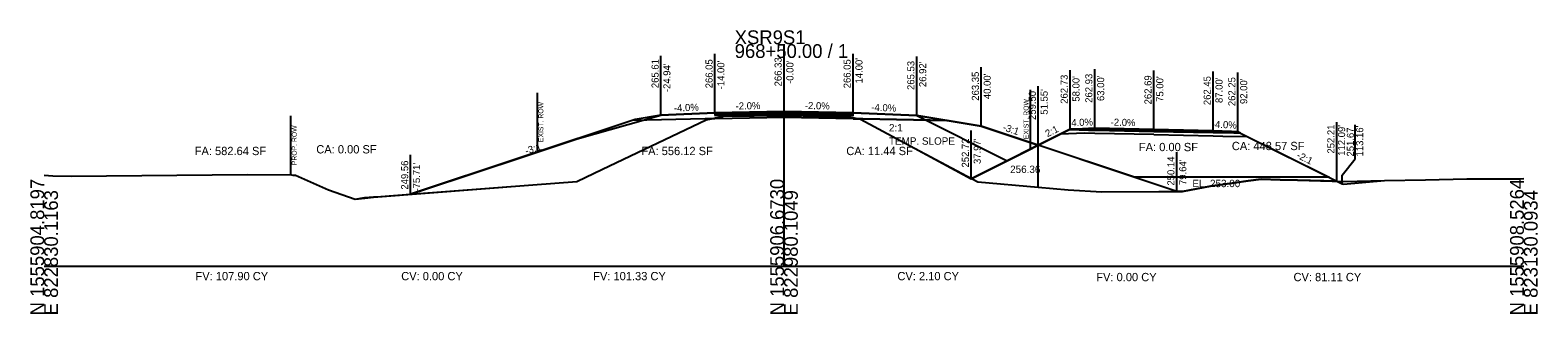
# Model space of a CAD drawing. Extents: x -26 to 823017, y -16 to 1558356.
# Drawn here: x 997.2 to 1302.8, y 8990.3 to 9047.8 of the extents above; entities that cross this region are included whole.
import ezdxf

# ---------------------------------------------------------------- set-up
doc = ezdxf.new("R2010")
doc.units = 0
for name, color, linetype in [('1', 7, 'Continuous'), ('ASPHALT_19MM1', 7, 'Continuous'), ('ASPHALT_9_5MM1', 7, 'Continuous'), ('CONST_DCH', 7, 'Continuous'), ('CONST_LV3', 7, 'Continuous'), ('Draft_XS_Grid', 7, 'Continuous'), ('DTM_CORRIDOR', 7, 'Continuous'), ('DTM_P_FINISHED_GRADE2', 7, 'Continuous'), ('DTM_X_GROUND', 7, 'Continuous'), ('SLOPE_STAKES_FILL', 7, 'Continuous'), ('X_PROFILES_1', 7, 'Continuous'), ('X_TRANS_EOP', 7, 'Continuous'), ('XS_CELL', 7, 'Continuous'), ('XS_M_SHAPES_EARTHWORK', 7, 'Continuous'), ('XS_P_DR_GRAVEL', 7, 'Continuous'), ('XS_P_GROUND', 7, 'Continuous'), ('XS_P_NULL_POINT', 7, 'Continuous'), ('XS_P_ROW', 7, 'Continuous'), ('XS_P_SHOULDER', 7, 'Continuous'), ('XS_P_SUBGRADE_GRANULAR', 7, 'Continuous'), ('XS_P_SUBGRADE_UNDERCUT', 7, 'Continuous'), ('XS_P_TX_CLEARZONE', 7, 'Continuous'), ('XS_P_TX_FS_BS', 7, 'Continuous'), ('XS_SHEET_EW_TX_AREA', 7, 'Continuous'), ('XS_SHEET_EW_TX_VOLUME', 7, 'Continuous'), ('XS_X_ROW', 7, 'Continuous')]:
    doc.layers.add(name, color=color, linetype=linetype)

msp = doc.modelspace()

# ---------------------------------------------------------------- linework, layer by layer
at = {"layer": '1'}
msp.add_lwpolyline([(1136, 9030.76), (1136, 9030.76), (1136, 9030.76), (1150, 9031.04), (1164, 9030.76), (1164, 9030.76), (1164, 9030.76), (1164, 9030.92), (1164, 9030.92), (1150, 9031.2), (1136, 9030.92), (1136, 9030.92), (1136, 9030.76)], dxfattribs=at)
at = {"layer": 'ASPHALT_19MM1'}
for points in [[(1136, 9030.55), (1136, 9030.55), (1136, 9030.55), (1150, 9030.83), (1164, 9030.55), (1164, 9030.55), (1164, 9030.55), (1164, 9030.76), (1164, 9030.76), (1150, 9031.04), (1136, 9030.76), (1136, 9030.76), (1136, 9030.55)], [(1213, 9027.56), (1225, 9027.32), (1237, 9027.08), (1237, 9027.28), (1225, 9027.52), (1213, 9027.76), (1213, 9027.56)]]:
    msp.add_lwpolyline(points, dxfattribs=at)
at = {"layer": 'ASPHALT_9_5MM1'}
msp.add_lwpolyline([(1136, 9030.92), (1136, 9030.92), (1136, 9030.92), (1150, 9031.2), (1164, 9030.92), (1164, 9030.92), (1164, 9030.92), (1164, 9031.05), (1164, 9031.05), (1150, 9031.33), (1136, 9031.05), (1136, 9031.05), (1136, 9030.92)], dxfattribs=at)
at = {"layer": 'CONST_LV3'}
for points in [[(1150, 9031.33), (1164, 9031.05)], [(1176.92, 9030.53), (1164, 9031.05), (1164, 9031.05)], [(1190, 9028.35), (1183.11, 9029.5), (1183.11, 9029.5)], [(1187.97, 9017.72), (1192.97, 9020.22), (1208, 9027.73), (1209.25, 9027.78), (1213, 9027.93)], [(1201.55, 9024.5), (1201.55, 9024.5), (1208, 9027.73), (1209.25, 9027.78), (1213, 9027.93), (1222.01, 9027.75), (1225, 9027.69), (1234.01, 9027.23), (1237, 9027.08), (1238.25, 9027.12), (1242, 9027.25), (1256.97, 9019.77), (1263.16, 9016.67), (1263.42, 9016.6), (1271.75, 9017.33), (1280.09, 9017.49), (1288.44, 9017.66), (1299.2, 9017.72), (1300, 9017.74)], [(1242, 9027.25), (1262.09, 9017.21)], [(1000, 9018.4), (1001.79, 9018.3), (1005.5, 9018.26), (1041.22, 9018.54), (1050.13, 9018.47), (1050.44, 9018.46), (1050.95, 9018.46), (1057.63, 9015.48), (1063.04, 9013.57), (1064.99, 9013.79), (1066.77, 9013.99), (1067.35, 9014.04), (1074.29, 9014.56)]]:
    msp.add_lwpolyline(points, dxfattribs=at)
at = {"layer": 'DTM_P_FINISHED_GRADE2'}
msp.add_lwpolyline([(1074.29, 9014.56), (1074.29, 9014.56), (1108.06, 9025.82), (1125.06, 9030.61), (1136, 9031.05), (1150, 9031.33), (1164, 9031.05), (1176.92, 9030.53), (1190, 9028.35), (1201.55, 9024.5)], dxfattribs=at)
at = {"layer": 'DTM_X_GROUND'}
for points in [[(1000, 9018.4), (1001.79, 9018.3), (1005.5, 9018.26), (1041.22, 9018.54), (1050.13, 9018.47), (1050.44, 9018.46), (1050.95, 9018.46), (1057.63, 9015.48), (1063.04, 9013.57), (1064.99, 9013.93), (1066.77, 9014.01), (1067.35, 9014.04), (1074.29, 9014.56), (1074.29, 9014.56), (1089.77, 9019.72), (1094.89, 9021.43), (1098.94, 9022.78), (1108.06, 9025.82), (1125.06, 9030.61), (1125.06, 9030.61), (1125.06, 9030.61), (1136, 9031.05), (1150, 9031.33), (1150, 9031.33), (1150, 9031.33), (1164, 9031.05), (1164, 9031.05), (1176.92, 9030.53), (1176.92, 9030.53), (1190, 9028.35), (1190, 9028.35), (1201.55, 9024.5), (1201.55, 9024.5), (1208, 9027.73), (1209.25, 9027.78), (1213, 9027.93), (1222.01, 9027.75), (1225, 9027.69), (1234.01, 9027.23), (1237, 9027.08), (1238.25, 9027.12), (1242, 9027.25), (1256.97, 9019.77), (1263.16, 9016.67), (1263.42, 9016.6), (1271.75, 9017.33), (1280.09, 9017.49), (1288.44, 9017.66), (1299.2, 9017.72), (1300, 9017.74)], [(1000, 9018.4), (1001.79, 9018.3), (1005.5, 9018.26), (1041.22, 9018.54), (1050.13, 9018.47), (1050.44, 9018.46), (1050.95, 9018.46), (1057.63, 9015.48), (1063.04, 9013.57), (1066.77, 9013.99), (1099.1, 9016.46), (1107.98, 9017.16), (1113.22, 9019.62), (1134.23, 9029.63), (1137.38, 9030.33), (1137.5, 9030.36), (1137.69, 9030.4), (1150.25, 9030.55), (1150.48, 9030.55), (1150.75, 9030.54), (1163.18, 9030.28), (1163.91, 9030.13), (1165.52, 9029.79), (1176.43, 9023.93), (1189.3, 9017.06), (1201.52, 9015.99), (1207.61, 9015.46), (1214.41, 9015.04), (1226, 9015.14), (1226.61, 9015.15), (1230.81, 9015.14), (1236.44, 9016.17), (1241.37, 9016.85), (1244.1, 9017.29), (1246.77, 9017.6), (1250.62, 9017.5), (1254.08, 9017.4), (1263.42, 9017.17), (1271.75, 9017.33), (1280.09, 9017.49), (1288.44, 9017.66), (1299.2, 9017.72), (1300, 9017.74)], [(1000, 9018.4), (1001.79, 9018.3), (1005.5, 9018.26), (1041.22, 9018.54), (1050.13, 9018.47), (1050.44, 9018.46), (1050.95, 9018.46), (1057.63, 9015.48), (1063.04, 9013.57), (1066.77, 9013.99), (1099.1, 9016.46), (1107.98, 9017.16), (1113.22, 9019.62), (1134.23, 9029.63), (1137.38, 9030.33), (1137.5, 9030.36), (1137.69, 9030.4), (1150.25, 9030.55), (1150.48, 9030.55), (1150.75, 9030.54), (1163.18, 9030.28), (1163.91, 9030.13), (1165.52, 9029.79), (1176.43, 9023.92), (1187.97, 9017.72), (1191.06, 9019.26), (1191.35, 9019.41), (1192.97, 9020.22), (1208, 9027.73), (1209.25, 9027.78), (1213, 9027.93), (1222.01, 9027.75), (1225, 9027.69), (1234.01, 9027.23), (1237, 9027.08), (1238.25, 9027.12), (1242, 9027.25), (1256.97, 9019.77), (1263.16, 9016.67), (1263.42, 9016.6), (1271.75, 9017.33), (1280.09, 9017.49), (1288.44, 9017.66), (1299.2, 9017.72), (1300, 9017.74)]]:
    msp.add_lwpolyline(points, dxfattribs=at)
at = {"layer": 'X_TRANS_EOP'}
msp.add_lwpolyline([(1213, 9027.76), (1225, 9027.52), (1237, 9027.28), (1237, 9027.45), (1225, 9027.69), (1213, 9027.93), (1213, 9027.76)], dxfattribs=at)
at = {"layer": 'XS_CELL'}
for p, q in [((1150, 9000), (1150, 9045)), ((1000, 9000), (1150, 9000)), ((1150, 9000), (1300, 9000))]:
    msp.add_line(p, q, dxfattribs=at)
at = {"layer": 'XS_M_SHAPES_EARTHWORK'}
for points in [[(1074.29, 9014.56), (1099.1, 9016.46), (1107.98, 9017.16), (1113.22, 9019.62), (1134.23, 9029.63), (1135.3, 9029.87), (1134, 9029.84), (1119.24, 9029.55)], [(1135.3, 9029.87), (1137.38, 9030.33), (1137.5, 9030.36), (1137.69, 9030.4), (1150.25, 9030.55), (1150.48, 9030.55), (1150.75, 9030.54), (1163.18, 9030.28), (1163.91, 9030.13), (1165.17, 9029.86), (1164, 9029.88), (1150, 9030.16), (1136, 9029.88)], [(1165.17, 9029.86), (1165.52, 9029.79), (1176.43, 9023.93), (1189.3, 9017.06), (1201.52, 9015.99), (1201.55, 9015.99), (1201.55, 9024.5), (1190, 9028.35), (1183.11, 9029.5), (1166, 9029.84)]]:
    msp.add_lwpolyline(points, close=True, dxfattribs=at)
at = {"layer": 'XS_P_DR_GRAVEL'}
for points in [[(1209.25, 9027.78), (1208, 9027.73), (1207.89, 9027.68), (1207.86, 9027.66), (1211.72, 9027.58), (1213, 9027.56), (1213, 9027.65), (1213, 9027.93), (1209.25, 9027.78)], [(1240.75, 9027.3), (1237, 9027.45), (1237, 9027.17), (1237, 9027.08), (1241.18, 9026.99), (1242.57, 9026.96), (1242.43, 9027.04), (1242, 9027.25), (1240.75, 9027.3)]]:
    msp.add_lwpolyline(points, dxfattribs=at)
at = {"layer": 'XS_P_GROUND'}
msp.add_line((1176.92, 9030.53), (1195.26, 9021.36), dxfattribs=at)
for points in [[(1125.06, 9030.61), (1119.81, 9029.74), (1074.29, 9014.56)], [(1176.92, 9030.53), (1190, 9028.35), (1201.55, 9024.5)], [(1229.64, 9015.14), (1229.64, 9015.14), (1190, 9028.35), (1176.92, 9030.53), (1176.92, 9030.53)], [(1208, 9027.73), (1187.97, 9017.72)], [(1242, 9027.25), (1263.16, 9016.67)], [(1262.09, 9017.21), (1262.09, 9017.21), (1262.09, 9017.21), (1254.08, 9017.4), (1254.08, 9017.4), (1250.62, 9017.5), (1250.62, 9017.5), (1246.77, 9017.6), (1246.77, 9017.6), (1244.1, 9017.29), (1241.37, 9016.85), (1241.37, 9016.85), (1236.44, 9016.17), (1236.44, 9016.17), (1236.44, 9016.17), (1230.81, 9015.14), (1230.81, 9015.14), (1229.64, 9015.14)], [(1262.09, 9017.21), (1262.09, 9017.21), (1262.09, 9017.21), (1254.08, 9017.4), (1254.08, 9017.4), (1250.62, 9017.5), (1250.62, 9017.5), (1246.77, 9017.6), (1246.77, 9017.6), (1244.1, 9017.29), (1241.37, 9016.85), (1241.37, 9016.85), (1236.44, 9016.17), (1236.44, 9016.17), (1236.44, 9016.17), (1230.81, 9015.14), (1230.81, 9015.14), (1229.64, 9015.14)]]:
    msp.add_lwpolyline(points, dxfattribs=at)
at = {"layer": 'XS_P_ROW'}
msp.add_line((1050, 9018.47), (1050, 9030.47), dxfattribs=at)
at = {"layer": 'XS_P_SHOULDER'}
for points in [[(1136, 9031.05), (1125.06, 9030.61)], [(1164, 9031.05), (1176.92, 9030.53)], [(1208, 9027.73), (1209.25, 9027.78), (1213, 9027.93)], [(1242, 9027.25), (1240.75, 9027.3), (1237, 9027.45)]]:
    msp.add_lwpolyline(points, dxfattribs=at)
at = {"layer": 'XS_P_SUBGRADE_GRANULAR'}
for points in [[(1136, 9029.88), (1134, 9029.84), (1119.24, 9029.55)], [(1150, 9030.16), (1136, 9029.88)], [(1164, 9029.88), (1164, 9029.88), (1150, 9030.16)], [(1164, 9029.88), (1166, 9029.84), (1183.11, 9029.5)], [(1213, 9026.89), (1211, 9026.93), (1206, 9026.73)], [(1225, 9026.65), (1213, 9026.89)], [(1225, 9026.65), (1237, 9026.41)], [(1237, 9026.41), (1239, 9026.37), (1243.96, 9026.27)]]:
    msp.add_lwpolyline(points, dxfattribs=at)
at = {"layer": 'XS_P_SUBGRADE_UNDERCUT'}
msp.add_lwpolyline([(1221.07, 9018), (1201.55, 9024.5), (1208, 9027.73), (1213, 9027.93), (1225, 9027.69), (1237, 9027.45), (1242, 9027.25), (1260.5, 9018)], close=True, dxfattribs=at)
at = {"layer": 'XS_P_TX_CLEARZONE'}
for p, q in [((1125.06, 9030.61), (1125.06, 9042.61)), ((1136, 9031.05), (1136, 9043.05)), ((1150, 9031.33), (1150, 9043.33)), ((1164, 9031.05), (1164, 9043.05)), ((1176.92, 9030.53), (1176.92, 9042.53)), ((1190, 9028.35), (1190, 9040.35)), ((1190, 9028.35), (1190, 9040.35)), ((1208, 9027.73), (1208, 9039.73)), ((1213, 9027.93), (1213, 9039.93)), ((1225, 9027.69), (1225, 9039.69)), ((1237, 9027.45), (1237, 9039.45)), ((1242, 9027.25), (1242, 9039.25)), ((1201.55, 9024.5), (1201.55, 9036.5)), ((1187.97, 9017.72), (1187.97, 9027.52)), ((1262.09, 9017.21), (1262.09, 9029.21)), ((1265.77, 9021.72), (1265.77, 9028.67)), ((1074.29, 9014.56), (1074.29, 9022.53)), ((1229.64, 9015.14), (1229.64, 9023.08)), ((1263.16, 9018.42), (1265.77, 9021.72)), ((1263.16, 9016.67), (1263.16, 9018.42))]:
    msp.add_line(p, q, dxfattribs=at)
at = {"layer": 'XS_X_ROW'}
for p, q in [((1100, 9023.14), (1100, 9035.14)), ((1200, 9023.73), (1200, 9035.73))]:
    msp.add_line(p, q, dxfattribs=at)

# ---------------------------------------------------------------- texts
at = {"layer": 'CONST_DCH'}
for p in [(1135.92, 9030.93), (1149.92, 9031.21), (1163.92, 9030.93)]:
    msp.add_text('X', height=0.24, dxfattribs=at).set_placement(p)
at = {"layer": 'CONST_LV3'}
for p in [(1176.84, 9030.41), (1189.92, 9028.23), (1201.47, 9024.38), (1074.21, 9014.44), (1229.56, 9015.02), (1262.01, 9017.09)]:
    msp.add_text('X', height=0.24, dxfattribs=at).set_placement(p)
at = {"layer": 'Draft_XS_Grid'}
msp.add_text('-', height=0.0001, dxfattribs=at).set_placement((1000, 9000))
at = {"layer": 'DTM_CORRIDOR'}
for p in [(1212.92, 9027.81), (1224.92, 9027.57), (1236.92, 9027.33)]:
    msp.add_text('X', height=0.24, dxfattribs=at).set_placement(p)
at = {"layer": 'SLOPE_STAKES_FILL'}
for p in [(1187.89, 9017.6), (1263.08, 9016.55)]:
    msp.add_text('X', height=0.24, dxfattribs=at).set_placement(p)
at = {"layer": 'X_PROFILES_1'}
msp.add_text('X', height=0.24, dxfattribs=at).set_placement((1262.01, 9017.09))
at = {"layer": 'XS_CELL'}
for s, p in [('XSR9S1', (1140, 9045)), ('968+50.00 / 1', (1140, 9042.2))]:
    msp.add_text(s, height=2.8, dxfattribs=at).set_placement(p)
for s, p in [('N 1555904.8197', (1000, 8990)), ('E 822830.1163', (1002.8, 8990)), ('N 1555906.6730', (1150, 8990)), ('E 822980.1049', (1152.8, 8990)), ('N 1555908.5264', (1300, 8990)), ('E 823130.0934', (1302.8, 8990))]:
    msp.add_text(s, height=2.8, rotation=90, dxfattribs=at).set_placement(p)
at = {"layer": 'XS_P_GROUND'}
for s, p in [('2:1', (1171.28, 9027.3)), ('TEMP. SLOPE', (1171.28, 9024.6)), ('256.36', (1195.85, 9018.87))]:
    msp.add_text(s, height=1.5, dxfattribs=at).set_placement(p)
at = {"layer": 'XS_P_NULL_POINT'}
for p in [(1201.47, 9024.38), (1187.89, 9017.6), (1074.21, 9014.44), (1263.08, 9016.55)]:
    msp.add_text('X', height=0.24, dxfattribs=at).set_placement(p)
at = {"layer": 'XS_P_ROW'}
msp.add_text('PROP. ROW', height=1, rotation=90, dxfattribs=at).set_placement((1051.2, 9020.47))
at = {"layer": 'XS_P_SHOULDER'}
for p in [(1124.98, 9030.49), (1176.84, 9030.41), (1207.92, 9027.61), (1241.92, 9027.13)]:
    msp.add_text('X', height=0.24, dxfattribs=at).set_placement(p)
at = {"layer": 'XS_P_SUBGRADE_GRANULAR'}
msp.add_text('X', height=0.24, dxfattribs=at).set_placement((1189.92, 9028.23))
at = {"layer": 'XS_P_SUBGRADE_UNDERCUT'}
msp.add_text('EL. 253.00', height=1.5, dxfattribs=at).set_placement((1232.8, 9016))
at = {"layer": 'XS_P_TX_CLEARZONE'}
for s, p in [('266.33', (1149.52, 9036.44)), ("14.00'", (1165.92, 9037.02)), ('265.61', (1124.58, 9036.08)), ("-24.94'", (1126.98, 9035.27)), ('266.05', (1135.52, 9036.05)), ("-14.00'", (1137.92, 9035.84)), ("-0.00'", (1151.92, 9036.94)), ('266.05', (1163.52, 9036.05)), ('265.53', (1176.44, 9035.71)), ("26.92'", (1178.84, 9036.3)), ('263.35', (1189.52, 9033.53)), ("40.00'", (1191.92, 9033.85)), ('262.73', (1207.52, 9032.91)), ("58.00'", (1209.92, 9033.34)), ('262.93', (1212.52, 9033.11)), ("63.00'", (1214.92, 9033.47)), ('262.69', (1224.52, 9032.79)), ("75.00'", (1226.92, 9033.3)), ('262.45', (1236.52, 9032.63)), ("87.00'", (1238.92, 9033.06)), ('262.25', (1241.52, 9032.43)), ("92.00'", (1243.92, 9032.86)), ('259.50', (1201.07, 9029.62)), ("51.55'", (1203.47, 9030.7)), ('252.21', (1261.61, 9022.81)), ("112.09'", (1263.77, 9022.36)), ('251.67', (1265.55, 9022.21)), ("113.16'", (1267.44, 9022.23)), ('252.72', (1187.49, 9019.99)), ("37.97'", (1189.89, 9020.69)), ('249.56', (1073.81, 9015.5)), ("-75.71'", (1076.21, 9015.11)), ('250.14', (1229.16, 9016.32)), ("79.64'", (1231.56, 9016.44))]:
    msp.add_text(s, height=1.44, rotation=90, dxfattribs=at).set_placement(p)
at = {"layer": 'XS_P_TX_FS_BS'}
for s, rotation, p in [('-4.0%', 2.2906, (1127.71, 9031.32)), ('-2.0%', 1.1458, (1140.2, 9031.73)), ('-2.0%', 358.8542, (1154.22, 9031.85)), ('-4.0%', 357.7094, (1167.69, 9031.5)), ('4.0%', 2.2906, (1208.27, 9028.34)), ('-2.0%', 358.8542, (1216.22, 9028.47)), ('-3:1', 341.5648, (1194.24, 9027.57)), ('2:1', 26.5651, (1203.41, 9026.11)), ('-4.0%', 357.7094, (1236.73, 9028.06)), ('-3:1', 17.54, (1097.76, 9022.61)), ('-2:1', 333.4326, (1253.79, 9022.01))]:
    msp.add_text(s, height=1.44, rotation=rotation, dxfattribs=at).set_placement(p)
at = {"layer": 'XS_SHEET_EW_TX_AREA'}
for s, p in [('FA: 582.64 SF', (1030.52, 9022.5)), ('CA: 0.00 SF', (1055.17, 9022.84)), ('FA: 556.12 SF', (1121.08, 9022.5)), ('CA: 11.44 SF', (1162.63, 9022.5)), ('FA: 0.00 SF', (1221.95, 9023.3)), ('CA: 448.57 SF', (1240.8, 9023.51))]:
    msp.add_text(s, height=1.68, dxfattribs=at).set_placement(p)
at = {"layer": 'XS_SHEET_EW_TX_VOLUME'}
for s, p in [('FV: 107.90 CY', (1030.68, 8997.12)), ('CV: 0.00 CY', (1072.39, 8997.12)), ('FV: 101.33 CY', (1111.31, 8997.12)), ('CV: 2.10 CY', (1172.99, 8997.12)), ('FV: 0.00 CY', (1213.31, 8996.93)), ('CV: 81.11 CY', (1253.3, 8996.93))]:
    msp.add_text(s, height=1.68, dxfattribs=at).set_placement(p)
at = {"layer": 'XS_X_ROW'}
for p in [(1101.2, 9025.14), (1199.58, 9025.73)]:
    msp.add_text('EXIST. ROW', height=1, rotation=90, dxfattribs=at).set_placement(p)

doc.saveas('drawing.dxf')
